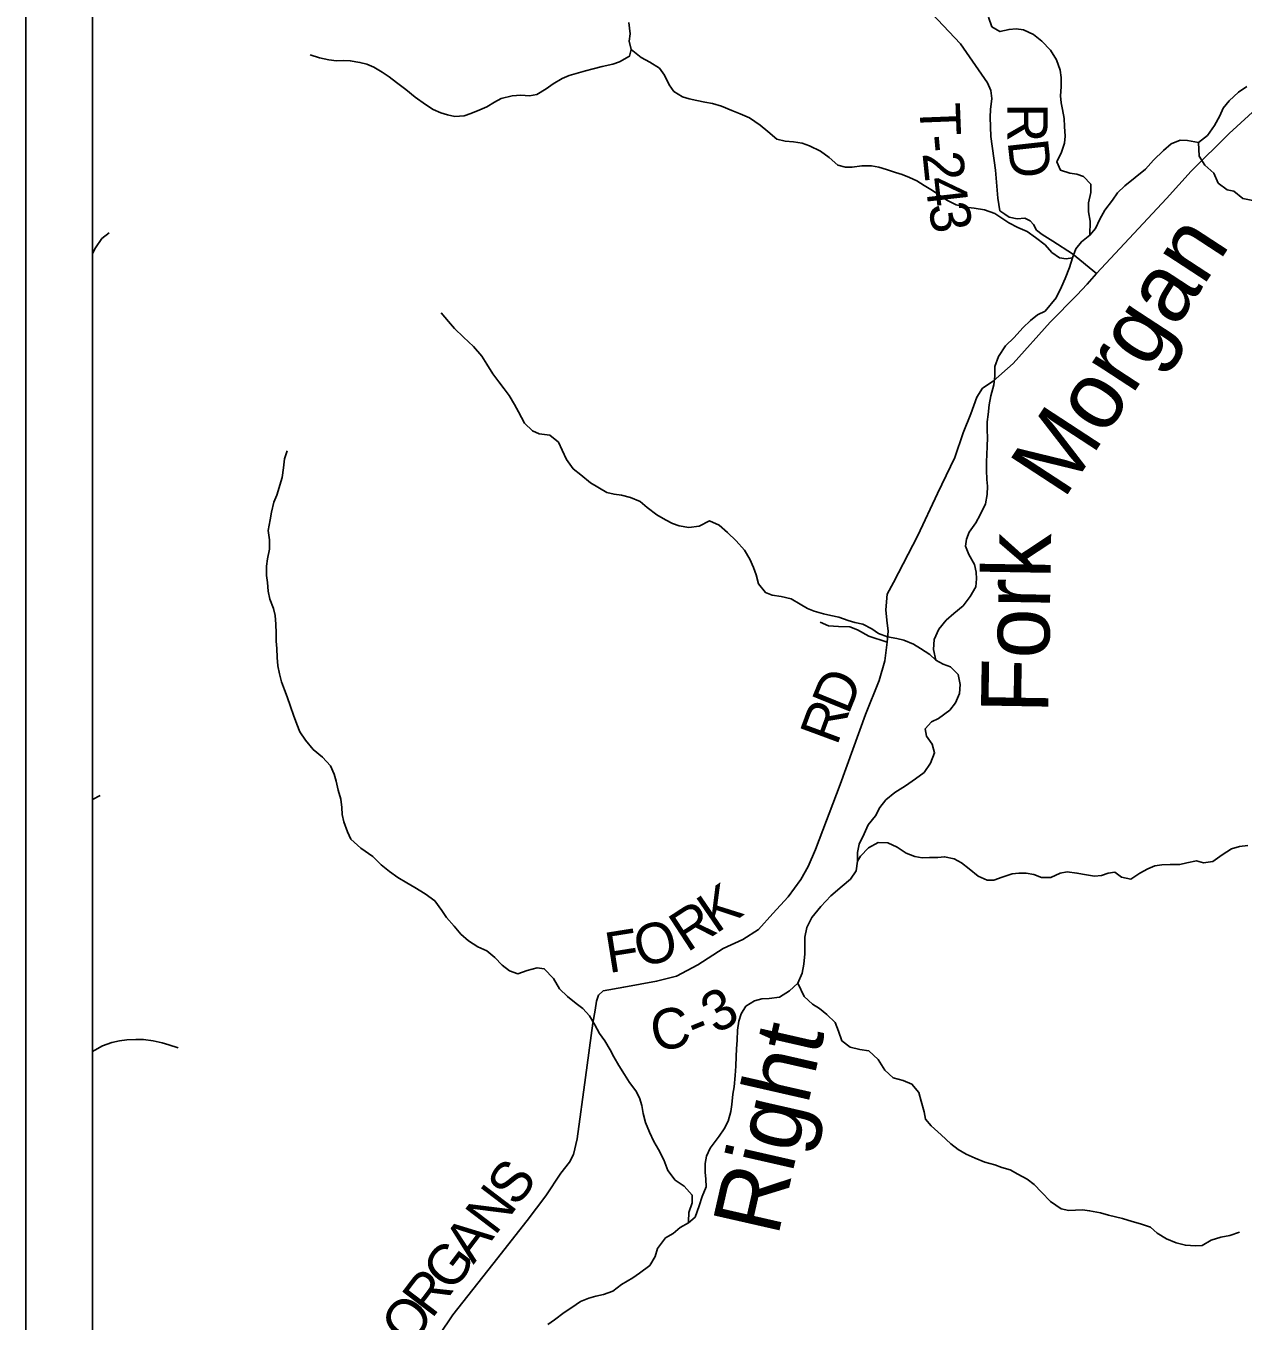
# Model space of a CAD drawing. Extents: x 0 to 34, y 0 to 22.
# Drawn here: x 2.106 to 3.817, y 16.76 to 18.581 of the extents above; entities that cross this region are included whole.
import ezdxf

# ---------------------------------------------------------------- set-up
doc = ezdxf.new("R2010")
doc.units = 0
for name, color, linetype in [('Default', 7, 'Continuous'), ('GM_X_County_Road', 7, 'Continuous'), ('GM_X_County_Road_Text', 7, 'Continuous'), ('GM_X_Minor_River', 7, 'Continuous'), ('GM_X_Minor_River_Text', 7, 'Continuous'), ('GM_X_Township_Road', 7, 'Continuous'), ('GM_X_Township_Road_Text', 7, 'Continuous'), ('SH_Cut_Line', 7, 'Continuous')]:
    doc.layers.add(name, color=color, linetype=linetype)

msp = doc.modelspace()

# ---------------------------------------------------------------- linework, layer by layer
at = {"layer": 'Default'}
msp.add_lwpolyline([(9.087, 13.8822), (2.1062, 13.8822), (2.1062, 20.9054), (9.087, 20.9054)], close=True, dxfattribs=at)
msp.add_lwpolyline([(4.7194, 16.7424), (4.6758, 16.8903), (4.9207, 17.3435), (4.9239, 17.3511), (4.937, 17.4953), (4.9996, 18.0806), (5.0018, 18.1008), (4.7661, 18.9124), (4.831, 19.2363), (4.7641, 19.2419), (3.1893, 19.3592), (2.7961, 19.3885), (2.2, 19.4329), (2.2, 14)], dxfattribs=at)
at = {"layer": 'GM_X_County_Road'}
msp.add_lwpolyline([(2.6678, 16.712), (2.7066, 16.7689), (2.7626, 16.84), (2.8109, 16.9014), (2.837, 16.9364), (2.8581, 16.968), (2.8704, 16.9835), (2.8762, 16.9944), (2.8813, 17.0164), (2.8932, 17.1028), (2.9035, 17.179), (2.9067, 17.1971), (2.9084, 17.21), (2.9111, 17.2184), (2.918, 17.2244), (2.9468, 17.2297), (2.993, 17.2379), (3.0211, 17.2452), (3.0508, 17.2612), (3.0865, 17.284), (3.1143, 17.2966), (3.136, 17.3108), (3.1563, 17.3333), (3.1781, 17.3566), (3.1957, 17.3811), (3.2062, 17.3992), (3.2162, 17.423), (3.2509, 17.5148), (3.2864, 17.6128), (3.3058, 17.6608), (3.314, 17.6884), (3.3173, 17.7149), (3.3186, 17.7301), (3.3165, 17.7457), (3.3152, 17.7601), (3.3169, 17.7821), (3.3258, 17.7987), (3.3602, 17.8647), (3.3877, 17.9237), (3.4124, 17.9742), (3.4241, 18.009), (3.4346, 18.0359), (3.4432, 18.0593), (3.4509, 18.0717), (3.4661, 18.0818), (3.494, 18.1066), (3.5464, 18.1644), (3.5839, 18.2027), (3.5983, 18.2182), (3.6115, 18.2332), (3.7098, 18.3383), (3.7443, 18.3767), (3.7978, 18.43), (3.8524, 18.4795)], dxfattribs=at)
at = {"layer": 'GM_X_Minor_River'}
msp.add_line((2.2, 17.4934), (2.2105, 17.4992), dxfattribs=at)
for points in [[(3.6022, 18.2867), (3.6024, 18.3066), (3.6002, 18.3195), (3.6002, 18.3325), (3.6032, 18.3469), (3.6032, 18.3587), (3.593, 18.3693), (3.5835, 18.3727), (3.5737, 18.3739), (3.5608, 18.3781), (3.5558, 18.3902), (3.5623, 18.4035), (3.5665, 18.4161), (3.5672, 18.426), (3.5665, 18.4396), (3.5657, 18.4507), (3.5635, 18.4636), (3.5616, 18.4731), (3.5608, 18.4826), (3.5616, 18.4955), (3.5616, 18.5085), (3.5601, 18.5191), (3.5552, 18.5332), (3.5468, 18.5472), (3.5343, 18.5598), (3.5226, 18.5689), (3.5089, 18.5754), (3.4983, 18.5769), (3.4884, 18.5761), (3.4755, 18.5731), (3.4642, 18.5799), (3.4596, 18.5932)], [(3.5778, 18.255), (3.5687, 18.2538), (3.5592, 18.2549), (3.5486, 18.2625), (3.5391, 18.2735), (3.5254, 18.2838), (3.5137, 18.2922), (3.5008, 18.2979), (3.4883, 18.3043), (3.4781, 18.3108), (3.4686, 18.3173), (3.4538, 18.3226), (3.4394, 18.3249), (3.4272, 18.3264), (3.4143, 18.3294), (3.4011, 18.3359), (3.3908, 18.3431), (3.3787, 18.3511), (3.3692, 18.3568), (3.3586, 18.3633), (3.3484, 18.3682), (3.3381, 18.3724), (3.3287, 18.375), (3.3161, 18.3792), (3.3055, 18.3823), (3.2949, 18.3842), (3.2816, 18.3842), (3.268, 18.3827), (3.2585, 18.3827), (3.2475, 18.3853), (3.2354, 18.3963), (3.2232, 18.4051), (3.2077, 18.4127), (3.1974, 18.4161), (3.1853, 18.418), (3.1739, 18.4191), (3.1618, 18.4218), (3.1493, 18.4325), (3.1387, 18.4416), (3.1235, 18.4518), (3.1106, 18.4575), (3.0985, 18.4621), (3.0844, 18.4682), (3.0716, 18.472), (3.0606, 18.4739), (3.0496, 18.4762), (3.0389, 18.4788), (3.0295, 18.4815), (3.0173, 18.4887), (3.0105, 18.4982), (3.0041, 18.5119), (2.9969, 18.5218), (2.9836, 18.5302), (2.9711, 18.5366), (2.9574, 18.548), (2.9544, 18.5598), (2.9559, 18.5701), (2.954, 18.586)], [(2.9574, 18.548), (2.9548, 18.5385), (2.9407, 18.5305), (2.9312, 18.5271), (2.9165, 18.5241), (2.9039, 18.5207), (2.8929, 18.518), (2.8831, 18.5153), (2.8698, 18.5112), (2.8603, 18.507), (2.8474, 18.4998), (2.8379, 18.4925), (2.8247, 18.4846), (2.8144, 18.483), (2.8019, 18.4838), (2.7901, 18.4827), (2.7746, 18.4789), (2.7651, 18.4739), (2.7541, 18.4675), (2.7442, 18.4633), (2.7317, 18.4579), (2.7222, 18.4549), (2.7093, 18.4538), (2.6991, 18.4561), (2.6896, 18.4591), (2.679, 18.4637), (2.668, 18.4705), (2.6536, 18.4811), (2.6403, 18.4918), (2.6274, 18.5017), (2.6168, 18.5097), (2.607, 18.5161), (2.5952, 18.5233), (2.5857, 18.5275), (2.5759, 18.5298), (2.5622, 18.5321), (2.5527, 18.5325), (2.5429, 18.5321), (2.5323, 18.5332), (2.519, 18.5363), (2.5061, 18.5405)], [(3.7675, 18.4268), (3.7771, 18.4412), (3.7847, 18.4548), (3.7893, 18.4654), (3.7981, 18.4756), (3.811, 18.488), (3.8228, 18.4959)], [(3.2001, 17.2622), (3.2014, 17.2766), (3.2015, 17.3001), (3.2042, 17.3134), (3.2111, 17.3277), (3.2237, 17.3432), (3.2378, 17.3579), (3.2537, 17.3715), (3.2655, 17.3817), (3.2735, 17.393), (3.2755, 17.407), (3.2756, 17.4188), (3.2775, 17.4309), (3.2848, 17.4453), (3.2906, 17.4578), (3.3005, 17.4706), (3.3066, 17.4823), (3.3153, 17.4929), (3.3279, 17.5031), (3.3427, 17.5125), (3.3567, 17.5226), (3.3693, 17.5316), (3.378, 17.5445), (3.3838, 17.5592), (3.3805, 17.5714), (3.3722, 17.5825), (3.3704, 17.5927), (3.3792, 17.6029), (3.3894, 17.6074), (3.4053, 17.6191), (3.4133, 17.6296), (3.4187, 17.6425), (3.4195, 17.6554), (3.417, 17.6691), (3.4061, 17.6798), (3.3959, 17.6836), (3.3857, 17.6894), (3.3824, 17.7046), (3.3833, 17.7186), (3.3898, 17.733), (3.4001, 17.7454), (3.4107, 17.7552), (3.424, 17.7658), (3.4339, 17.779), (3.4416, 17.7926), (3.4428, 17.8036), (3.4424, 17.8131), (3.4399, 17.8237), (3.432, 17.8378), (3.4272, 17.8496), (3.4284, 17.8595), (3.4322, 17.8693), (3.4417, 17.8825), (3.4478, 17.8939), (3.4551, 17.909), (3.4575, 17.9223), (3.4583, 17.934), (3.4572, 17.9435), (3.4565, 17.9564), (3.4566, 17.9682), (3.4571, 17.9784), (3.4575, 17.9898), (3.458, 18.0023), (3.4576, 18.0126), (3.4577, 18.0243), (3.4589, 18.0349), (3.4605, 18.0482), (3.4628, 18.0611), (3.4671, 18.0763), (3.4683, 18.0888), (3.4684, 18.1024), (3.4738, 18.1164), (3.4833, 18.1312), (3.4955, 18.1429), (3.508, 18.1568), (3.5187, 18.167), (3.5286, 18.1749), (3.5392, 18.1801), (3.5548, 18.1986), (3.5621, 18.2141), (3.5671, 18.2259), (3.5732, 18.2414), (3.5778, 18.255), (3.5824, 18.2675), (3.5901, 18.2777), (3.6022, 18.2867), (3.6102, 18.2965), (3.6163, 18.3094), (3.6232, 18.3219), (3.6339, 18.3362), (3.6411, 18.3464), (3.651, 18.3562), (3.6658, 18.3679), (3.6803, 18.3799), (3.6917, 18.3924), (3.7054, 18.406), (3.7164, 18.4154), (3.7289, 18.4206), (3.7391, 18.4198), (3.7546, 18.4174), (3.7675, 18.4268)], [(3.7546, 18.4174), (3.7557, 18.3982), (3.7637, 18.3853), (3.7762, 18.3743), (3.7823, 18.3602), (3.7951, 18.3507), (3.8046, 18.3488), (3.8171, 18.3385), (3.8429, 18.3332)], [(2.2, 18.2612), (2.2041, 18.2691), (2.2132, 18.282), (2.2234, 18.29)], [(3.3857, 17.6894), (3.3772, 17.6972), (3.364, 17.7056), (3.3541, 17.7121), (3.3404, 17.7174), (3.3306, 17.7197), (3.3177, 17.7223), (3.3048, 17.7269), (3.2953, 17.7334), (3.2828, 17.7398), (3.2718, 17.7425), (3.2623, 17.7451), (3.2491, 17.7497), (3.2381, 17.752), (3.2278, 17.7543), (3.2146, 17.7581), (3.2051, 17.7619), (3.1948, 17.7683), (3.1819, 17.7756), (3.1679, 17.779), (3.1554, 17.7809), (3.1459, 17.7847), (3.1361, 17.7969), (3.1327, 17.8094), (3.1293, 17.8197), (3.1239, 17.8315), (3.1167, 17.844), (3.1046, 17.8573), (3.0925, 17.8687), (3.0807, 17.8794), (3.0671, 17.8851), (3.0527, 17.8778), (3.0383, 17.8759), (3.0246, 17.8782), (3.0151, 17.8816), (3.0056, 17.8866), (2.9931, 17.8938), (2.9799, 17.9041), (2.9696, 17.9124), (2.956, 17.9181), (2.9438, 17.9212), (2.9332, 17.9227), (2.923, 17.925), (2.9002, 17.9387), (2.8862, 17.9501), (2.8756, 17.9584), (2.8661, 17.9717), (2.8601, 17.9847), (2.8548, 17.9961), (2.843, 18.0056), (2.8278, 18.0075), (2.8184, 18.0117), (2.807, 18.0227), (2.7986, 18.0383), (2.793, 18.0489), (2.7858, 18.0615), (2.7786, 18.071), (2.771, 18.0805), (2.7626, 18.0919), (2.7543, 18.1056), (2.7471, 18.1166), (2.7354, 18.1303), (2.7213, 18.1436), (2.7088, 18.1557), (2.7005, 18.1656), (2.6899, 18.1778)], [(3.0376, 16.8985), (3.0377, 16.9004), (3.0381, 16.913), (3.0431, 16.9263), (3.0431, 16.9373), (3.0317, 16.9498), (3.0192, 16.9582), (3.0086, 16.9719), (3.0033, 16.9871), (2.9957, 17.0015), (2.9889, 17.0126), (2.9828, 17.0259), (2.9771, 17.0392), (2.9741, 17.0521), (2.9722, 17.0635), (2.9688, 17.0742), (2.9635, 17.0837), (2.9548, 17.0954), (2.948, 17.1068), (2.94, 17.1194), (2.9328, 17.1319), (2.9275, 17.1414), (2.9203, 17.154), (2.9127, 17.1643), (2.9063, 17.1768), (2.8987, 17.1893), (2.8892, 17.1996), (2.8798, 17.2065), (2.8676, 17.2167), (2.8566, 17.2274), (2.8479, 17.2418), (2.835, 17.2555), (2.8248, 17.2566), (2.8111, 17.2532), (2.7979, 17.2483), (2.7861, 17.2528), (2.7759, 17.2604), (2.7653, 17.2715), (2.7543, 17.2806), (2.7414, 17.2863), (2.7285, 17.2947), (2.7179, 17.3042), (2.7084, 17.3156), (2.6974, 17.3274), (2.691, 17.3372), (2.6811, 17.3509), (2.6675, 17.3608), (2.653, 17.3696), (2.6417, 17.3764), (2.6292, 17.384), (2.6174, 17.3924), (2.6057, 17.4015), (2.5939, 17.4133), (2.5772, 17.4251), (2.5632, 17.4376), (2.5583, 17.4479), (2.5534, 17.4619), (2.5511, 17.4726), (2.5503, 17.4821), (2.5488, 17.4939), (2.5454, 17.5068), (2.5424, 17.5194), (2.5394, 17.5292), (2.5344, 17.5406), (2.5234, 17.5528), (2.5102, 17.5638), (2.4992, 17.5771), (2.4912, 17.5886), (2.4871, 17.5992), (2.4825, 17.6121), (2.4783, 17.6243), (2.4734, 17.6376), (2.4696, 17.6479), (2.4658, 17.6589), (2.4628, 17.6703), (2.4605, 17.6813), (2.4594, 17.6931), (2.459, 17.706), (2.4583, 17.7159), (2.4583, 17.7273), (2.4575, 17.7402), (2.4568, 17.752), (2.4545, 17.7619), (2.4492, 17.7752), (2.4469, 17.7862), (2.4458, 17.7984), (2.4447, 17.8083), (2.4443, 17.8216), (2.4458, 17.8319), (2.4485, 17.8456), (2.4489, 17.8585), (2.447, 17.8718), (2.4497, 17.8866), (2.4516, 17.8973), (2.455, 17.9113), (2.4591, 17.9212), (2.4667, 17.9463), (2.4686, 17.9596), (2.4698, 17.9725), (2.4736, 17.9839)], [(3.2755, 17.407), (3.2796, 17.414), (3.291, 17.4254), (3.3043, 17.433), (3.3179, 17.4327), (3.3312, 17.4266), (3.3437, 17.4182), (3.3558, 17.4133), (3.3665, 17.4117), (3.3767, 17.4121), (3.3881, 17.4121), (3.3979, 17.4129), (3.4112, 17.4102), (3.4214, 17.4045), (3.4324, 17.3961), (3.445, 17.3859), (3.4575, 17.3802), (3.4669, 17.3802), (3.4787, 17.3844), (3.4927, 17.3889), (3.5022, 17.3901), (3.5125, 17.3901), (3.5231, 17.3882), (3.5341, 17.384), (3.5474, 17.3836), (3.5602, 17.3901), (3.5701, 17.3916), (3.5838, 17.3901), (3.5974, 17.3874), (3.6088, 17.3855), (3.6183, 17.3866), (3.6278, 17.3901), (3.6372, 17.3912), (3.6467, 17.3844), (3.6596, 17.3817), (3.6725, 17.3901), (3.6835, 17.3961), (3.6934, 17.4003), (3.7032, 17.4015), (3.715, 17.4022), (3.7287, 17.4022), (3.7385, 17.4045), (3.7518, 17.4072), (3.7617, 17.4045), (3.7749, 17.4064), (3.7882, 17.4159), (3.8011, 17.4239), (3.8125, 17.4273), (3.8242, 17.4288)], [(2.8398, 16.7552), (2.8493, 16.762), (2.8629, 16.7721), (2.8739, 16.7793), (2.8861, 16.7875), (2.8975, 16.7924), (2.9077, 16.7954), (2.9183, 16.7976), (2.9316, 16.8024), (2.9437, 16.8115), (2.9593, 16.8212), (2.9691, 16.8276), (2.9832, 16.8385), (2.9908, 16.851), (2.9943, 16.8624), (3.0054, 16.8771), (3.0164, 16.8835), (3.0259, 16.8918), (3.0376, 16.8985), (3.0471, 16.9064), (3.0529, 16.922), (3.0571, 16.9352), (3.0625, 16.9488), (3.0622, 16.9595), (3.0611, 16.9697), (3.0612, 16.9815), (3.0631, 16.9921), (3.0681, 17.0031), (3.0807, 17.0201), (3.088, 17.0303), (3.0937, 17.0412), (3.0972, 17.0549), (3.0987, 17.0647), (3.1003, 17.0791), (3.1019, 17.0894), (3.1035, 17.1053), (3.1044, 17.1186), (3.1048, 17.1322), (3.1053, 17.1429), (3.1061, 17.155), (3.1066, 17.169), (3.1085, 17.1819), (3.112, 17.1921), (3.1185, 17.2027), (3.1306, 17.2106), (3.1409, 17.2132), (3.1511, 17.2139), (3.1655, 17.2157), (3.1799, 17.2243), (3.1917, 17.2353), (3.1978, 17.2493), (3.2001, 17.2622)], [(3.1917, 17.2353), (3.2002, 17.2167), (3.212, 17.2057), (3.2218, 17.1996), (3.2321, 17.1912), (3.2438, 17.1802), (3.2488, 17.1677), (3.2533, 17.1544), (3.2651, 17.1452), (3.2787, 17.1422), (3.2912, 17.1399), (3.3045, 17.1281), (3.314, 17.1129), (3.3257, 17.1023), (3.3394, 17.0985), (3.3519, 17.0935), (3.3617, 17.0817), (3.3651, 17.0692), (3.3689, 17.0544), (3.3712, 17.0441), (3.3791, 17.0346), (3.3928, 17.0221), (3.4068, 17.0095), (3.4167, 17.0015), (3.4281, 16.9947), (3.4409, 16.9894), (3.4546, 16.9837), (3.4686, 16.9799), (3.4785, 16.9761), (3.4899, 16.9726), (3.5009, 16.9669), (3.5137, 16.9597), (3.5236, 16.9521), (3.5342, 16.9415), (3.5467, 16.9281), (3.5619, 16.9179), (3.5725, 16.9156), (3.582, 16.916), (3.5915, 16.9167), (3.6017, 16.9152), (3.6169, 16.9122), (3.6283, 16.9091), (3.648, 16.9046), (3.6616, 16.9004), (3.6734, 16.897), (3.6874, 16.892), (3.6969, 16.884), (3.7098, 16.8757), (3.7234, 16.87), (3.7363, 16.8669), (3.7504, 16.8658), (3.7598, 16.8665), (3.7727, 16.8738), (3.786, 16.8783), (3.7989, 16.8806), (3.8122, 16.8852)], [(2.2, 17.1391), (2.2031, 17.1411), (2.2138, 17.1472), (2.227, 17.1517), (2.2376, 17.154), (2.2479, 17.1555), (2.2608, 17.1563), (2.2714, 17.1559), (2.2851, 17.1544), (2.2976, 17.1514), (2.3071, 17.1487), (2.3203, 17.1445)]]:
    msp.add_lwpolyline(points, dxfattribs=at)
at = {"layer": 'GM_X_Township_Road'}
for points in [[(3.6115, 18.2332), (3.5777, 18.2605), (3.5499, 18.2783), (3.5349, 18.2879), (3.527, 18.2941), (3.5226, 18.3021), (3.5181, 18.3071), (3.5106, 18.311), (3.5, 18.3099), (3.4887, 18.3123), (3.4823, 18.3162), (3.4755, 18.3212), (3.4727, 18.3391), (3.4693, 18.3782), (3.463, 18.4257), (3.4618, 18.4527), (3.4623, 18.4637), (3.464, 18.4789), (3.463, 18.4903), (3.4582, 18.5013), (3.4202, 18.556), (3.3798, 18.5986)], [(3.2231, 17.7429), (3.2348, 17.7378), (3.2488, 17.7365), (3.2646, 17.7364), (3.2756, 17.7321), (3.2913, 17.7232), (3.3173, 17.7149)]]:
    msp.add_lwpolyline(points, dxfattribs=at)
at = {"layer": 'SH_Cut_Line'}
msp.add_lwpolyline([(2.2, 19.4329), (2.2, 14), (9, 14), (9, 18.8941), (8.8762, 18.9027), (8.0305, 18.9725), (6.8442, 19.0679), (6.226, 19.1161), (5.8337, 19.1499), (5.3224, 19.1939), (5.1554, 19.2083), (4.831, 19.2363), (4.7641, 19.2419), (3.1893, 19.3592), (2.7961, 19.3885)], close=True, dxfattribs=at)

# ---------------------------------------------------------------- texts
at = {"layer": 'GM_X_County_Road_Text'}
for s, rotation, p in [('D', 67.9097, (3.2624, 17.6113)), ('R', 69.7048, (3.2464, 17.568)), ('K', 34.4135, (3.0761, 17.3039)), ('R', 33.0883, (3.0358, 17.2777)), ('O', 15.1584, (2.9699, 17.2567)), ('F', 9.0319, (2.9255, 17.2493)), ('3', 29.425, (3.0763, 17.1629)), ('C', 11.1385, (2.9904, 17.1383)), ('-', 21.9852, (3.0474, 17.1507)), ('S', 53.2138, (2.7962, 16.9191)), ('N', 52.7314, (2.7656, 16.8789)), ('A', 52.7179, (2.7354, 16.8391)), ('G', 52.7199, (2.7051, 16.7993)), ('R', 52.7187, (2.6768, 16.7622)), ('O', 52.717, (2.6465, 16.7224))]:
    msp.add_text(s, height=0.0568, rotation=rotation, dxfattribs=at).set_placement(p)
at = {"layer": 'GM_X_Minor_River_Text'}
for s, height, rotation, p in [('Morgan', 0.09469, 56.8456, (3.5652, 17.9139)), ('Fork', 0.0947, 89.0485, (3.5435, 17.6137)), ('Right', 0.0947, 77.1717, (3.1634, 16.8776))]:
    msp.add_text(s, height=height, rotation=rotation, dxfattribs=at).set_placement(p)
at = {"layer": 'GM_X_Township_Road_Text'}
for s, rotation, p in [('T', 272.2377, (3.3625, 18.4718)), ('R', 269.7385, (3.4861, 18.4725)), ('-', 275.0938, (3.3644, 18.4263)), ('D', 276.3456, (3.4863, 18.4188)), ('2', 275.9869, (3.3666, 18.4021)), ('4', 276.4689, (3.3703, 18.3667)), ('3', 279.5823, (3.3747, 18.3286))]:
    msp.add_text(s, height=0.0568, rotation=rotation, dxfattribs=at).set_placement(p)

doc.saveas('drawing.dxf')
